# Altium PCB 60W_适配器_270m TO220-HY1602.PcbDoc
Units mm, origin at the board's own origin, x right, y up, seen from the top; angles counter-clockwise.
Board outline 43.1 x 72.7 mm, 2 copper layers (Top Layer, Bottom Layer); 70 components, 100 nets, 175 pads, 0 vias.
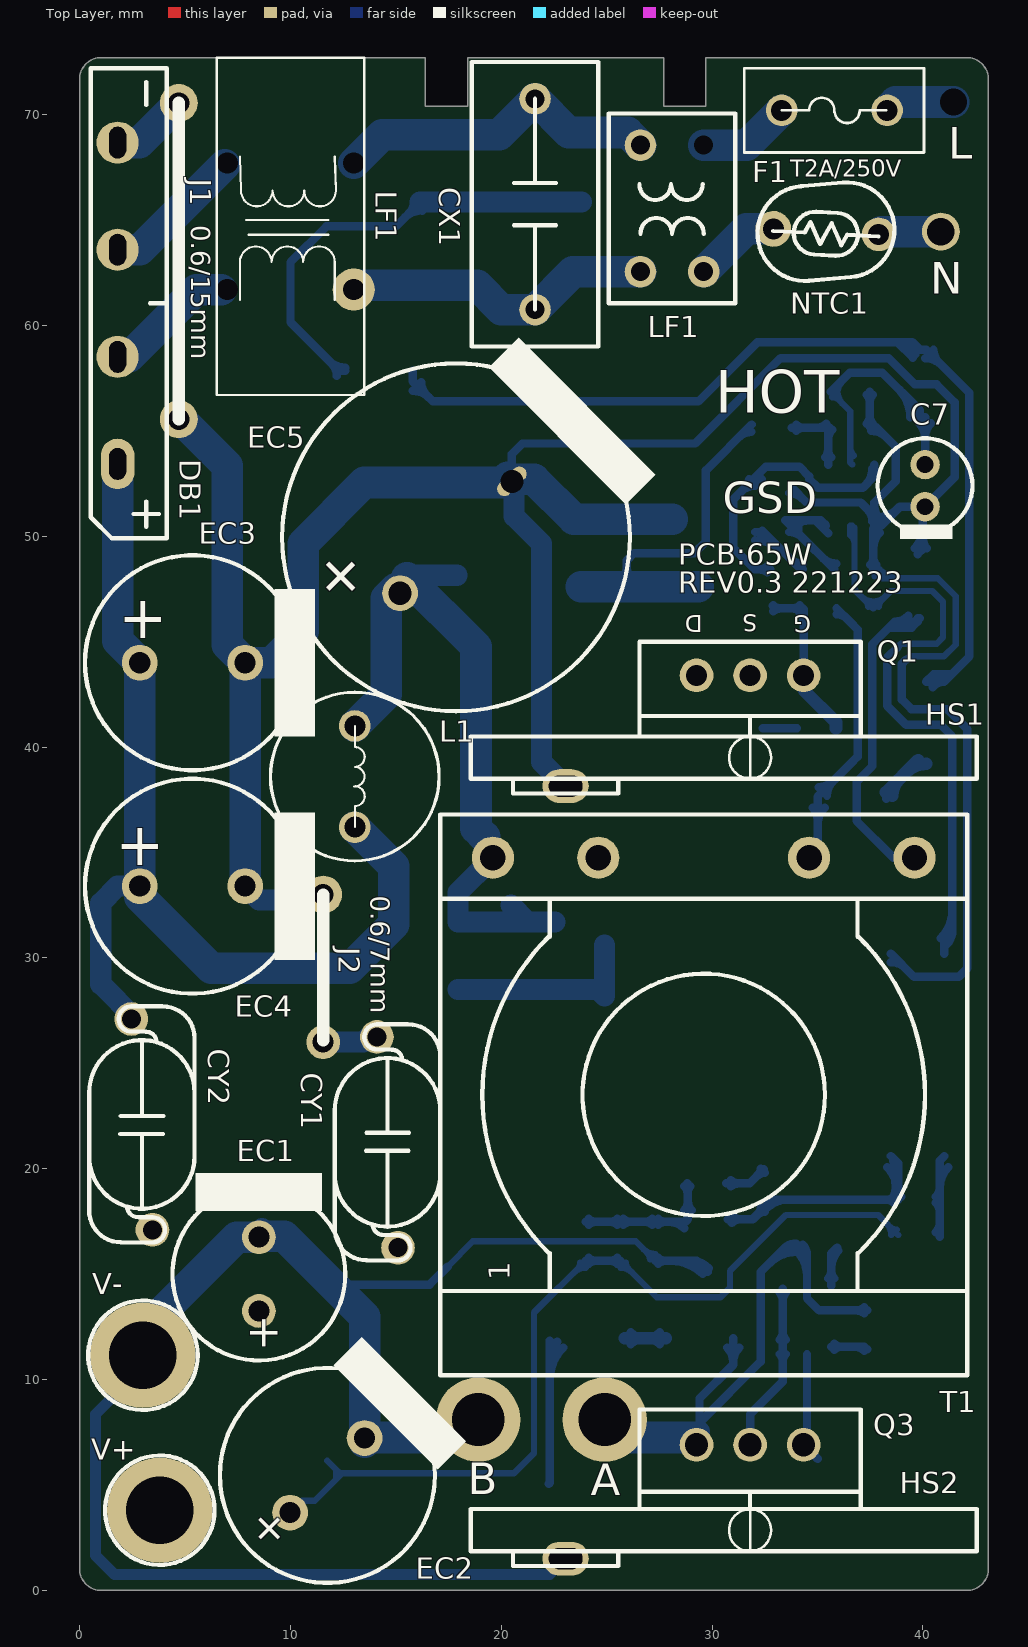
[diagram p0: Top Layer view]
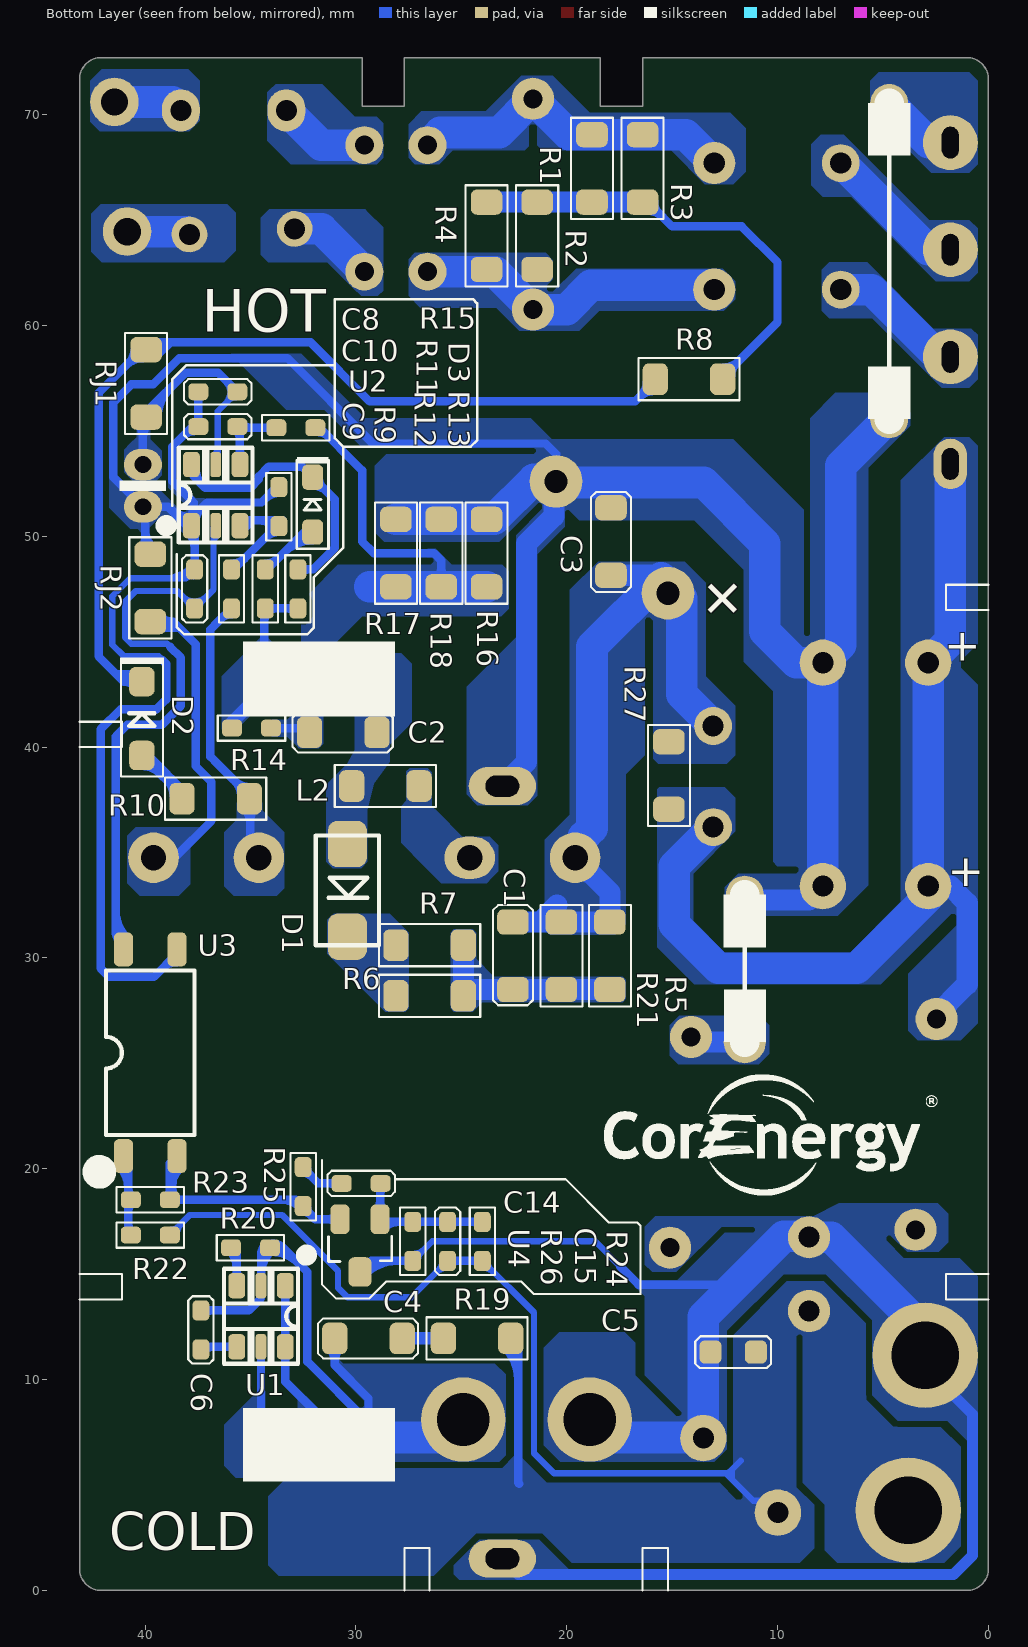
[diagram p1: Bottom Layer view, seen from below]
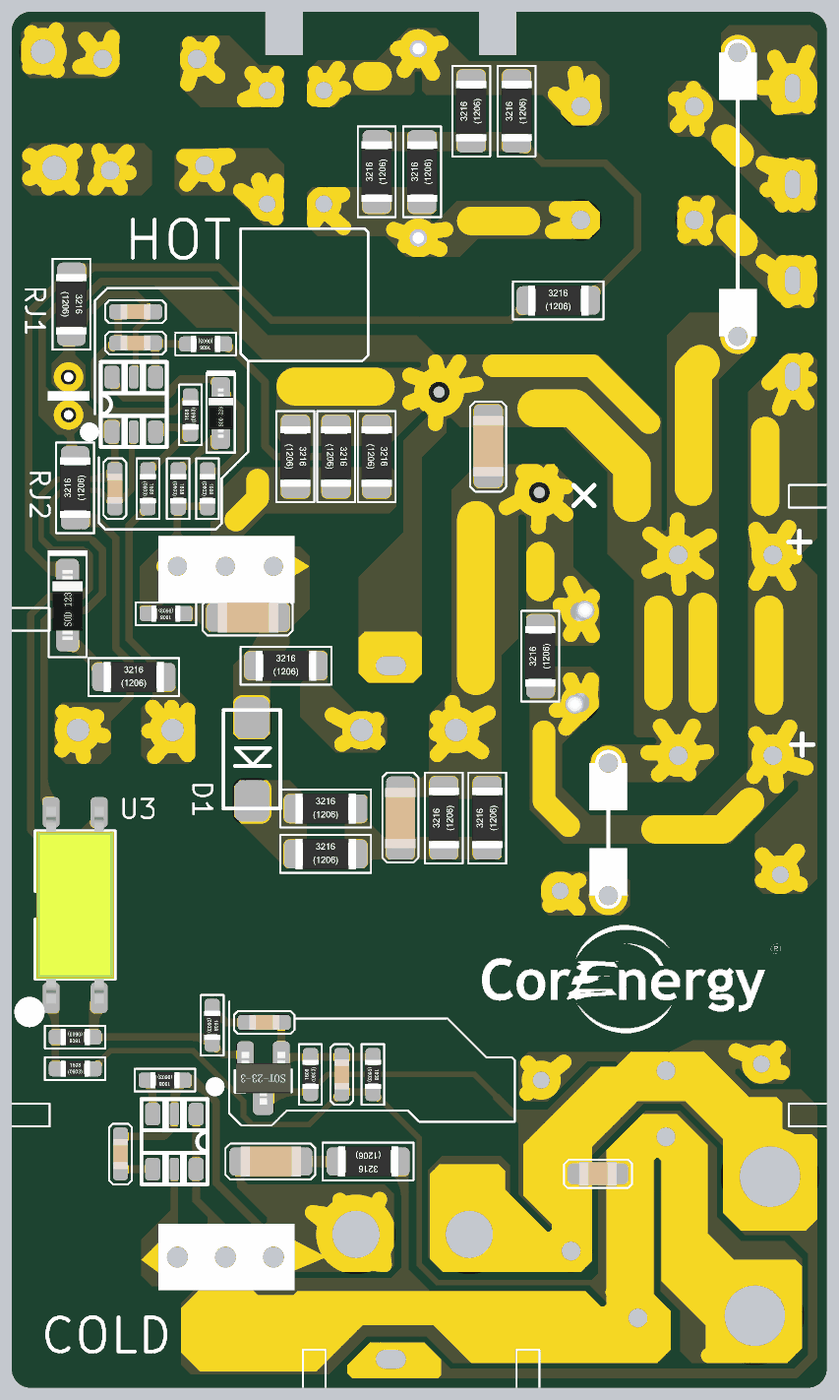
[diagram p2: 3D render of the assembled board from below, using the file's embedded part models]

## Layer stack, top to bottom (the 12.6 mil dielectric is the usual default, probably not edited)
Top Layer: signal copper 0.0356
Dielectric: dielectric 0.32, FR-4, Dk 4.8
Bottom Layer: signal copper 0.0356

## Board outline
0,1 ccw(c1,1) 1,0 42.1,0 ccw(c42.1,1) 43.1,1 43.1,71.7 ccw(c42.1,71.7) 42.1,72.7 29.7,72.7 29.7,70.4 27.7,70.4 27.7,72.7 18.4,72.7 18.4,70.4 16.4,70.4 16.4,72.7 1,72.7 ccw(c1,71.7) 0,71.7

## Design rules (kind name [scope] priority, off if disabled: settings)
AssemblyTestPointUsage [All] p1 off:
AssemblyTestpoint [All] p1 off: testpointundercomponent=TRUE minsize=1.016 maxsize=2.54 preferedsize=1.524 minholesize=0 maxholesize=1.016 preferedholesize=0.813 testpointgrid=0.025 usegrid=TRUE gridtolerance=0 allowsidetop=TRUE allowsidebottom=TRUE
Clearance [All] p1: gap=0.3
ComponentClearance [All] p1 off: gap=0.254 collisioncheckmode=3 verticalgap=0.254 showdistances=FALSE
DiffPairsRouting [All] p1 off: maxlimit=0.254 minlimit=0.254 mostfreqgap=0.254 maxuncoupledlength=12.7
FabricationTestPointUsage [All] p1 off: valid=0 allowmultiple=FALSE
FabricationTestpoint [All] p1 off: side=3 testpointundercomponent=TRUE minsize=1.016 maxsize=2.54 preferedsize=1.524 minholesize=0 maxholesize=1.016 preferedholesize=0.813 testpointgrid=0.025 allowsidetop=TRUE allowsidebottom=TRUE usegrid=TRUE gridtolerance=0
FanoutControl Fanout_BGA [IsBGA] p1 off: bgadir=Out bgaviamode=Centered fanoutstyle=Auto fanoutdirection=Alternating viagrid=0.025 // Fanout_BGA (Default Rule)
FanoutControl Fanout_LCC [IsLCC] p2 off: bgadir=Out bgaviamode=Centered fanoutstyle=Auto fanoutdirection=Alternating viagrid=0.025 // Fanout_LCC (Default Rule)
FanoutControl Fanout_SOIC [IsSOIC] p3 off: bgadir=Out bgaviamode=Centered fanoutstyle=Auto fanoutdirection=Alternating viagrid=0.025 // Fanout_SOIC (Default Rule)
FanoutControl Fanout_Small [(CompPinCount < 5)] p4 off: bgadir=Out bgaviamode=Centered fanoutstyle=Auto fanoutdirection=OutThenIn viagrid=0.025 // Fanout_Small (Default Rule)
FanoutControl Fanout_Default [All] p5 off: bgadir=Out bgaviamode=Centered fanoutstyle=Auto fanoutdirection=Alternating viagrid=0.025 // Fanout_Default (Default Rule)
Height [All] p1 off: minheight=0 maxheight=25.4 prefheight=12.7
HoleSize [All] p1 off: absolutevalues=TRUE maxlimit=2.54 minlimit=0.025 maxpercent=80.000 minpercent=20.000
HoleToHoleClearance [All] p1 off: gap=0.254 allowstackedmicrovias=TRUE
LayerPairs [All] p1 off: enforce=TRUE
MinimumSolderMaskSliver [All] p1 off: minsoldermaskwidth=0.254
NetAntennae [All] p1 off: netantennaetolerance=0
PasteMaskExpansion [All] p1 off: expansion=0
PlaneClearance [All] p1 off: clearance=0.508
PlaneConnect [All] p1 off: planeconnectstyle=Direct reliefexpansion=0.508 reliefentries=4 reliefconductorwidth=0.254 reliefairgap=0.254
PolygonConnect PolygonConnect_1 [All] p1: connectstyle=Direct reliefconductorwidth=0.254 reliefentries=4 polygonreliefangle="90 Angle" airgapwidth=0.254
RoutingCorners [All] p1 off: cornerstyle=45-Degree minsetback=2.54 maxsetback=2.54
RoutingLayers [All] p1 off: top layer_v5=TRUE bottom layer_v5=TRUE
RoutingPriority [All] p1 off: routingpriority=0
RoutingTopology [All] p1 off: topology=Shortest
RoutingVias [All] p1: holewidth=0.4 width=0.7 viastyle="Through Hole" minholewidth=0.3 minwidth=0.5 maxholewidth=1 maxwidth=1.5
SilkToSilkClearance [All] p1 off: silktosilkclearance=0.254
SilkToSolderMaskClearance [IsPad] p1 off: minsilkscreentomaskgap=0.254 clearancetoexposedcopper=TRUE
SolderMaskExpansion [All] p1 off: expansion=0.102
Width [All] p1: maxlimit=10 minlimit=0.2 preferedwidth=0.4
2 further rules are at their usual default settings.

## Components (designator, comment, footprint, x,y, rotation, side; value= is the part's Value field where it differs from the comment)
C1 "10nF/500V" 1206C 22.55,30.1 r270 bottom
C2 "10nF/500V" 1206C 30.6,40.7 r180 bottom (schematic designator C1)
C3 "10nF/500V" 1206C 17.9,49.75 r90 bottom
C4 "1nF/250V" 1206C 29.4,11.95 r180 bottom
C5 "4.7uF/25V 0805" 0805C 12.1,11.3 r180 bottom
C6 "0.22uF/50V" 0603C 37.35,12.35 r90 bottom
C7 "4.7uF 1206 50V D5*H10" EC-4X7-P2-C-1 40.1,52.4 r270 top
C8 "100nF 50V 0603" 0603C 36.55,56.85 r0 bottom
C9 "1nF/50V" 0603C 37.65,47.5 r90 bottom
C10 "100pF/50V" 0603C 36.55,55.2 r0 bottom
C14 "100nF/50v" 0603C 29.75,19.3 r180 bottom
C15 "100nF/50v" 0603C 25.65,16.55 r90 bottom (schematic designator C14)
CX1 "0.22uF/275Vac" XC-13X6-P10 21.6,65.75 r90 top
CY1 "1000pF/400Vac" YC-8X6-P10-V 14.6,21.25 r270 top
CY2 "1000pF/400Vac" YC-8X6-P10-V 2.95,22.1 r90 top (schematic designator CY1)
D1 "RS2M  SMAF" SMAF 30.4,33.2 r270 bottom
D2 "FR107 SOD123" 123 40.15,41.35 r270 bottom
D3 "1N4148 SOD323" 323 32.05,51.5 r270 bottom
DB1 "YBSM6008" BD-22X3.4-P5.08-+ 2,61.05 r270 top (schematic designator BD100)
EC1 "E - Cap" EC8 8.5,15 r90 top (schematic designator EC7)
EC2 "E - Cap" EC10 11.75,5.45 r45 top (schematic designator EC7)
EC3 "47uF/400V/13*19" EC10 5.35,44 r0 top (schematic designator EC1)
EC4 "47uF/400V/13*19" EC10 5.35,33.4 r0 top (schematic designator EC1)
EC5 "47uF/400V/13*19" EC-16X21-P7.5-C 17.85,49.95 r45 top (schematic designator EC1)
F1 "T2A/250V" FUSE 35.8,70.2 r90 top
HS1 "Comment" HS-PIN6 23.05,38.15 r180 top
HS2 "Comment" HS-PIN6 23.05,1.5 r180 top
J1 "Comment" JUMP-0.6/15 4.7,70.55 r270 top
J2 "Comment" JUMP-0.6/7.5 11.55,33 r270 top
L1 "HWR8*12/40uH" T8*10 13.05,38.6 r270 top
L2 "" 1206R 28.6,38.15 r180 bottom
LF1 "T6*3*3/100uH" T10*6*5 10,64.7 r90 top
LF1 "Comment" T9*5*3 28.1,65.55 r270 top
NTC1 "5D-7" NTC-6.5X4.5-P5 35.4,64.45 r185 top
Q1 "Comment" Cascode-TO220-3L-T 31.8,43.4 r180 top
Q3 "Comment" TO-220-3P-P2.54 31.8,6.9 r180 top
R1 "3.6M 1/2W" 1206R 18.8,67.45 r90 bottom
R2 "3.6M 1/2W" 1206R 21.4,64.25 r90 bottom
R3 "3.6M 1/2W" 1206R 16.4,67.45 r90 bottom
R4 "3.6M 1/2W" 1206R 23.8,64.25 r90 bottom
R5 "390K 1/2W" 1206R 17.95,30.1 r90 bottom
R6 "47R 1/2W" 1206R 26.5,28.2 r180 bottom
R7 "47R 1/2W" 1206R 26.5,30.6 r180 bottom
R8 "100K  1206" 1206R 14.2,57.45 r180 bottom
R9 "130K 0603" 0603R 35.9,47.5 r270 bottom
R10 "0805 磁珠/2.2R 0805" 1206R 36.65,37.55 r180 bottom
R11 "27K 0603" 0603R 33.65,51.4 r90 bottom
R12 "82R  1/10W 0603" 0603R 34.3,47.5 r270 bottom
R13 "10R 1/16W 0402" 0603R 32.75,47.5 r270 bottom
R14 "10K 0603" 0603R 34.95,40.9 r0 bottom
R15 "470R 0603" 0603R 32.85,55.15 r0 bottom
R16 "0R75 1/2W 1206" 1206R 23.8,49.2 r270 bottom
R17 "0R75 1/2W 1206" 1206R 28.1,49.2 r270 bottom
R18 "0R75 1/2W 1206" 1206R 25.95,49.2 r270 bottom
R19 "10R 1206" 1206R 24.25,11.95 r0 bottom
R20 "51K 0402" 0603R 35,16.25 r0 bottom
R21 "390K 1/2W" 1206R 20.25,30.1 r90 bottom (schematic designator R5)
R22 "2K" 0603R 39.75,16.85 r180 bottom
R23 "5.1K" 0603R 39.75,18.525 r0 bottom
R24 "24K" 0603R 24,16.55 r270 bottom
R25 "10K" 0603R 32.5,19.15 r270 bottom
R26 "3.16K" 0603R 27.3,16.55 r90 bottom
R27 "390K 1/2W" 1206R 15.15,38.65 r90 bottom (schematic designator R5)
RJ1 "150K/1206" 1206R 39.95,57.25 r270 bottom (schematic designator R9)
RJ2 "150K/1206" 1206R 39.75,47.55 r90 bottom (schematic designator R9)
T1 "Comment" EQ25 29.6,23.5 r0 top locked
U1 "MP6908/MK91808" SOT-23-6 34.5,13 r270 bottom
U2 "MK2697" SOT-23-6 36.65,51.95 r90 bottom
U3 "Comment" SO-4(P10)-超薄 39.75,25.5 r180 bottom
U4 "" SOT-23 29.8,16.35 r0 bottom

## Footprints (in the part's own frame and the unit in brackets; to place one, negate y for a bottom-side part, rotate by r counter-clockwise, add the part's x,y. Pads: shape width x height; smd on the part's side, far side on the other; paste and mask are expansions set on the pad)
123 [mm]
  rrect50% 1.4x1.2 smd mask+0.03: 1(1.75,0) 2(-1.75,0)
  silkscreen extent -2.9,-1.05 2.75,1.05, body extent -1.85,-0.8 1.85,0.8, height 1.2
323 [mm]
  rrect50% 1.2x1 smd mask+0.03: 1(1.3,0) 2(-1.3,0)
  silkscreen extent -2.25,-0.75 2.1,0.75, body extent -1.3,-0.65 1.3,0.65, height 1
0603C [mm]
  rrect50% 0.95x0.8 smd mask+0.03: 1(-0.925,0) 2(0.925,0)
  silkscreen extent -1.6,-0.6 1.6,0.6, body extent -0.8,-0.4 0.8,0.4, height 0.8
0603R [mm]
  rrect50% 0.95x0.8 smd mask+0.03: 1(-0.925,0) 2(0.925,0)
  silkscreen extent -1.6,-0.6 1.6,0.6, body extent -0.77,-0.42 0.78,0.43, height 0.45
0805C [mm]
  rrect50% 1.05x1.1 smd mask+0.03: 1(-1.075,0) 2(1.075,0)
  silkscreen extent -1.8,-0.75 1.8,0.75, body extent -1,-0.62 1,0.63, height 0.6
1206C [mm]
  rrect50% 1.2x1.5 smd mask+0.03: 1(-1.6,0) 2(1.6,0)
  silkscreen extent -2.4,-0.95 2.35,0.95, body extent -1.6,-0.8 1.6,0.8, height 0.79
1206R [mm]
  rrect50% 1.2x1.5 smd mask+0.03: 1(-1.6,0) 2(1.6,0)
  silkscreen extent -2.4,-1 2.4,1, body extent -1.6,-0.8 1.6,0.8, height 0.55
BD-22X3.4-P5.08-+ [mm]
  oval 2.4x1.6 hole 0.8 slot 1.5 at 0 deg mask+0.03: 1(7.62,-0.2)
  round 2 / inner round 2.6 / far side round 2.6 hole 0.8 slot 1.5 at 0 deg mask+0.03: 2(2.54,-0.2) 3(-2.54,-0.2) 4(-7.62,-0.2)
  silkscreen extent -11.15,-1.47 11.15,2.13
Cascode-TO220-3L-T [mm]
  round 1.6 / inner oval 1.6x2.6 / far side oval 1.6x2.6 hole 1 mask+0.03: 1(-2.54,0) 3(0,0)
  round 1.6 / inner oval 1.6x2.6 / far side oval 1.6x2 hole 1 mask+0.03: 2(2.54,0)
  silkscreen extent -5.25,-1.6 5.25,2.9, body extent -5.1,-1.35 5.1,2.85, height 1.1
EC8 [mm]
  round 1.6 / inner round 2 / far side round 2 hole 1 mask+0.03: 1(-1.75,0) 2(1.75,0)
  silkscreen extent -4.1,-4.1 4.8,4.1
EC10 [mm]
  round 1.7 / inner round 2.2 / far side round 2.2 hole 1 mask+0.03: 1(-2.5,0) 2(2.5,0)
  silkscreen extent -5.1,-5.1 5.8,5.1
EC-4X7-P2-C-1 [mm]
  round 1.4 / inner round 1.4 / far side oval 1.5x1.8 hole 0.8 mask+0.03: 1(-1,0) 2(1,0)
  silkscreen extent -2.25,-2.25 2.53,2.25, body extent -2.25,-2.25 2.25,2.25, height 8.6
EC-16X21-P7.5-C [mm]
  round 1.7 / inner round 2.5 / far side round 2.5 hole 1.1 mask+0.064: 1(-3.75,0)
  oval 1.7x0.7 / inner round 2.5 / far side round 2.5 hole 1.1 mask+0.064: 2(3.75,0)
  silkscreen extent -8.25,-8.25 8.8,8.25, body extent -8.1,-8.1 8.1,8.1, height 22.05
EQ25 [mm]
  round 2 on Mech2 mask+0.03: 1(-10,-11.25) 2(-5,-11.25) 3(0,-11.25) 4(5,-11.25) 5(10,-11.25) 8(0,11.25)
  round 2 / inner round 2 / far side round 2.4 hole 1.2 mask+0.03: 6(10,11.25) 7(5,11.25) 10(-10,11.25)
  round 2 / inner round 2 / far side oval 2.4x2 hole 1.2 mask+0.03: 9(-5,11.25)
  silkscreen extent -12.5,-13.3 12.5,13.3
FUSE [mm]
  round 1.5 / inner oval 2x1.8 / far side oval 2x1.8 hole 1 mask+0.03: 1(0,-2.5) 2(0,2.5)
  silkscreen extent -2,-4.25 2,4.28
HS-PIN6 [mm]
  oval 2.2x1.6 / inner oval 3.2x2.5 / far side oval 3.2x1.8 hole 1 slot 1.6 at 0 deg mask+0.03: 1(0,0)
  silkscreen extent -2.5,-0.35 2.5,0.35
JUMP-0.6/7.5 [mm]
  oval 3.5x2 on Mech2 mask+0.03: 0(0.75,0) 0(6.25,0)
  round 1.8 hole 1 mask+0.03: 1(0,0)
  round 1.6 / inner round 2 / far side round 2 hole 1 mask+0.03: 2(7,0)
  silkscreen extent 0,0 6.9,0
JUMP-0.6/15 [mm]
  oval 3.5x2 on Mech2 mask+0.03: 0(0.75,0) 0(14.25,0)
  round 1.8 hole 1 mask+0.03: 1(0,0) 2(15,0)
  silkscreen extent 0,0 15,0
NTC-6.5X4.5-P5 [mm]
  round 1.6 / inner round 1.7 / far side round 1.7 hole 1 mask+0.03: 1(-2.476,0.348)
  round 1.7 hole 1 mask+0.03: 2(2.476,-0.348)
  silkscreen extent -3.25,-2.25 3.25,2.25
SMAF [mm]
  rrect50% 2.2x1.85 smd: 1(-2.2,0) 2(2.2,0)
  silkscreen extent -2.6,-1.5 2.6,1.5
SO-4(P10)-超薄 [mm]
  rrect50% 0.9x1.6 smd mask+0.03: 1(-1.27,-4.9) 2(1.27,-4.9) 3(1.27,4.9) 4(-1.27,4.9)
  silkscreen extent -2.82,-6.05 2.1,3.9, body extent -2.05,-5.2 2.05,5.2, height 2.5
SOT-23 [mm]
  rrect50% 0.9x1.4 smd mask+0.03: 1(-0.95,-1.25) 3(0.95,-1.25)
  rrect50% 1.1x1.4 smd mask+0.03: 2(0,1.25)
  silkscreen extent -1.5,-0.45 1.5,0.75, body extent -1.45,-1.4 1.45,1.4, height 1.2
SOT-23-6 [mm]
  rrect50% 1.2x0.8 smd mask+0.03: 1(-1.45,1.15) 3(-1.45,-1.15) 4(1.45,-1.15) 6(1.45,1.15)
  rrect50% 1.2x0.5 smd mask+0.03: 2(-1.45,0) 5(1.45,0)
  silkscreen extent -3.15,-1.75 2.25,2.4
T8*10 [mm] "磁环电感"
  round 1.5 / inner round 1.5 / far side round 1.8 hole 1: 1(-2.4,0) 2(2.4,0)
  silkscreen extent -4,-4 4,4, body extent -3.5,-3.5 3.5,3.5, height 10.92
T9*5*3 [mm]
  round 1.5 / inner round 1.8 / far side round 1.8 hole 0.9 mask+0.03: 1(3,1.5) 3(-3,-1.5) 4(3,-1.5)
  round 0 / inner round 1.8 / far side round 1.8 hole 0.9 mask+0.03: 2(-3,1.5)
  silkscreen extent -4.5,-3 4.5,3
T10*6*5 [mm] "磁环电感"
  round 0 / inner round 1 / far side round 1.8 hole 1: 1(3,3)
  round 2 hole 1: 2(-3,-3)
  round 0 / inner round 1 / far side round 2 hole 1: 3(3,-3)
  round 0 / inner round 1.8 / far side round 1.8 hole 1: 4(-3,3)
  silkscreen extent -8,-3.5 8,3.5
TO-220-3P-P2.54 [mm]
  round 1.6 / inner oval 1.9x2.6 / far side oval 1.9x2.6 hole 1.1 mask+0.03: 1(-2.54,0) 2(0,0) 3(2.54,0)
  silkscreen extent -5.25,-1.67 5.25,3.05
XC-13X6-P10 [mm]
  round 1.5 / inner round 2 / far side round 2 hole 0.9 mask+0.03: 1(-5,0) 2(5,0)
  silkscreen extent -6.75,-3 6.75,3, body extent -6.5,-3 6.5,3, height 11.2
YC-8X6-P10-V [mm]
  round 1.6 / inner round 2 / far side round 2 hole 0.9 mask+0.03: 1(-5,-0.5) 2(5,0.5)
  silkscreen extent -5.6,-2.5 5.6,2.5

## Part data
C1 C2 C3 C4 C5 C6 C8 C9 C10 C14 C15: library part CAPACITOR
C7: library part E-CAP
CX1: library part R21030006, "R21030006/工业C/消费A/金属膜电容/0.1uF±10%/275Vac/X2/聚炳烯/引脚间距10mm"
CY1 CY2: library part R21020185, "R21020185/工业C/消费C/瓷片电容/220pF±10%/400Vac/Y1/Y5P/P=10mm/Y脚编带"
D1 D2 D3: library part DIODE
DB1: library part BRIDGE, "1000V/6A， YBS3,YANGJIE(扬杰)"
EC1 EC2: "Electroytic Capacitor, 100uF/35V, ±20%, 105℃，Φ 6.5 * 12.0 mm"
EC3 EC4 EC5: library part R21010448, "R21010448/工业B/消费B/铝电解电容/105℃/33uF/400V/φ13*25"
F1: library part FUSE, "FUSE"
L1: library part IND-C, "ferrite inductor"
L2: library part Inductor, "Inductor"
LF1: library part L-T12*6*6
NTC1: library part RT-NTC-SCH
R1 R2 R3 R4 R5 R6 R7 R8 R9 R10 R11 R12 R13 R15 R16 R17 R18 R19 R20 R21 R22 R23 R24 R25 R26 R27: library part RESISTOR
R14: library part RES, "RES"
RJ1 RJ2: library part R20140036, "R20140036/工业A/消费A/贴片电阻/1/4W/150KΩ±5%/1206"
U1: library part MK91808
U4: library part "IC TL431", "IC"

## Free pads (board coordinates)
  round 5 hole 3.2: 0(3,11.15) 0(3.8,3.8)
  round 1.8 / inner round 2.3 / far side round 2.3 hole 1.3: 3(40.85,64.45)
  round 0 / inner round 2.3 / far side round 2.3 hole 1.3: 3(41.45,70.6)
  round 4 hole 2.5: B(18.9,8.1) B(24.9,8.1)

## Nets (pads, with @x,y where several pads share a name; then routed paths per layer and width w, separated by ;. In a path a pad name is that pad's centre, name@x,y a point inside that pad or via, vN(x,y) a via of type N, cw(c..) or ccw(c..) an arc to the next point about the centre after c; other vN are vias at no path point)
12V: 
111: 
115: 
116: F1.2 LF1.2@29.6,68.55 | length 4.4
  Bottom Layer w1.5: LF1.2@29.6,68.55 31.65,68.55 F1.2
117: LF1.1@29.6,62.55 NTC1.2 | length 4.1
  Bottom Layer w1.5: LF1.1@29.6,62.55 31.631,64.581 NTC1.2
AGND: 
COMP: C9.1 U2.2 U3.4 | length 35.2
  Bottom Layer w0.3: U2.2@36.55,50.5 36.55,50.05 36.75,49.85 ; U2.2@36.579,50.079 cw(c36.167,49.667) 36.75,49.667 ; U2.2@36.607,50.06 cw(c36.5,49.834) 36.75,49.834 ; U2.2 36.75,50.4 36.75,49.85 ; U2.2@36.731,50.091 ccw(c36.882,49.982) 36.75,49.85 ; 37.095,47.13 ccw(c37.65,47.685) 37.65,46.9 ccw(c37.65,47.685) 38.205,47.13 ; C9.1@37.276,46.949 cw(c36.978,46.65) C9.1@37.4,46.65 ; C9.1@37.9,46.65 cw(c38.322,46.65) C9.1@38.024,46.949 ; 38.81,44.75 38.96,44.9 40.65,44.9 40.95,45.2 40.95,46.9 40.45,47.4 38.475,47.4 C9.1 36.75,47.475 36.75,49.85
  Bottom Layer w0.4: 38.81,44.75 38.3,44.24 38.3,41.96 39.21,41.05 40.85,41.05 41.375,40.525 ; U3.4@40.843,30.927 ccw(c39.499,32.271) 41.4,32.271 ; U3.4@41.02,30.2 41.02,30.77 41.4,31.15 41.4,40.5 ; U3.4@41.126,30.644 ccw(c40.465,31.305) 41.4,31.305
D: 
DGND: 
FB_IC1: 
GND: C3.2 C7.2 C8.2 C9.2 C10.2 CY1.1 DB1.4 EC3.2 EC4.2 EC5.2 HS1.1 J1.1 J1.2 J2.1 J2.2 R11.2 R16.1 R17.1 R18.1 RJ2.1 RJ2.2 T1.6 U2.1 U3.3 | length 185.6
  Bottom Layer w0.3: C9.2@37.615,48.315 ccw(c38.374,49.074) 38.374,48 ; C9.2 38.075,48 ; C9.2@37.706,48.106 cw(c37.794,47.719) 38.075,48 ; C9.2@37.827,48.527 ccw(c39.099,49.799) 39.099,48 ; C9.2@37.9,48.35 ccw(c38.322,48.35) C9.2@38.024,48.051 ; 39.2,44.15 39.35,44.3 41,44.3 41.55,44.85 41.55,47.149 40.699,48 38.075,48
  Bottom Layer w0.4: EC5.2@20.502,52.802 20.502,53.902 21,54.4 29.2,54.4 33.25,58.45 38.369,58.45 39.619,57.2 40.65,57.2 41.5,56.35 41.5,52.8 C7.2 C7.2@40,51.4 ; R11.2@33.65,52.05 cw(c33.65,51.145) 34.29,51.785 ; R11.2@33.8,52.275 34.475,51.6 37.05,51.6 U2.1@37.7,50.95 ; C10.2@37.334,55.341 ccw(c36.992,55.683) 37.475,55.683 ccw(c37.958,55.683) C10.2@37.616,55.341 ; C8.2@37.334,56.709 cw(c36.992,56.367) 37.475,56.367 cw(c37.958,56.367) C8.2@37.616,56.709 ; 37.353,51.297 cw(c36.755,50.7) U2.1@37.6,50.7 ; C8.2 C10.2 37.75,55.2 38.7,54.25 38.7,52.6 37.7,51.6 U2.1@37.7,50.5 ; C9.2@37.509,48.641 ccw(c37.167,48.983) 37.65,48.983 ccw(c38.133,48.983) C9.2@37.791,48.641 ; C10.2@37.55,55 cw(c37.55,54.034) 38.233,54.717 ; 37.6,44.4 37.6,44.88 38.385,45.665 ; 37.6,44.53 37.6,39.1 37.25,38.75 36.85,38.35 36.85,36.5 38.6,34.75 T1.6 ; C9.2 37.65,50.35 U2.1 38,50.5 38.9,51.4 C7.2@40,51.4 ; 37.65,49.455 cw(c38.645,49.455) U2.1@37.941,50.159 ; 37.7,51.424 ccw(c38.524,51.424) U2.1@37.941,50.841 ; U2.1@37.8,50.9 ccw(c37.8,52.349) 38.824,51.324 ; U3.3@38.48,29.8 cw(c38.48,28.834) 39.163,29.517 ; U3.3@38.48,30.2 39.58,29.1 41.7,29.1 42.1,29.5 42.1,40.85 41.15,41.8 39.45,41.8 39,42.25 39,43.95 39.2,44.15 ; RJ2.1@39.31,45.675 ccw(c38.67,45.069) 38.67,45.95 ; RJ2.1@39.31,46.225 cw(c38.67,46.831) 38.67,45.95 ; RJ2.2@39.617,49.433 ccw(c38.693,50.357) 40,50.357 ; RJ2.1@39.75,46.1 RJ2.1@39.85,46.1 ; RJ2.2 40,49.4 C7.2@40,51.4 ; 40,49.874 ccw(c40.624,49.874) RJ2.2@40.183,49.433 ; 38.385,45.665 39.465,45.665 RJ2.1 38.67,45.95 ; 38.385,45.665 38.67,45.95
  Bottom Layer w1: EC4.2 8.5,32.75 J2.1@11.65,32.75 ; J2.2 13.45,26 CY1.1@13.7,26.25 ; EC5.2@20.2,52.552 20.6,52.152 20.6,50.95 21.9,49.65 21.9,39.3 HS1.1
  Bottom Layer w1.5: DB1.4 2.82,68.67 J1.1 ; J1.2@5.15,55.2 7,53.35 7,44.85 EC3.2 ; EC4.2 EC3.2 ; EC5.2@20.2,52.552 13.502,52.552 10.6,49.65 10.6,45.5 9.1,44 EC3.2 ; EC5.2@20.302,52.802 EC5.2@20.376,52.727 ; EC5.2@20.402,52.702 21.548,52.702 23.45,50.8 R16.1 R18.1 R17.1
HV: C1.1 C3.1 EC5.1 L1.1 R5.2 R21.2 R27.2 T1.10 | length 33
  Bottom Layer w1: EC5.1@15.525,48.025 15.65,48.15 C3.1 ; T1.10 17.95,33.1 R5.2 R21.2 21.25,31.7 ; 20.45,32.5 21.25,31.7 ; C1.1 21.25,31.7
  Bottom Layer w1.5: L1.1 14.55,42.5 14.55,47.05 EC5.1@14.998,47.498 ; EC5.1@15.525,48.025 18.8,44.75 18.8,36.15 T1.10@19.2,35.75
IC1_CS: 
IC1_GD: 
L: 
L1: 
N: 
N1: 
NetC1_1: 
NetC1_2: C1.2 R5.1 R6.2 R7.2 R21.1 | length 9.5
  Bottom Layer w1: R5.1 R21.1 C1.2 24.6,28.5 R6.2 R7.2
NetC2_1: 
NetC2_2: L2.2 T1.9
NetC4_1: 
NetC4_2: C4.2 R19.2 | length 5
  Bottom Layer w0.4: R19.2@26.133,11.667 cw(c26.816,10.984) 26.816,11.95 cw(c26.816,12.916) R19.2@26.133,12.233 ; C4.2@27.517,11.667 ccw(c26.834,10.984) 26.834,11.95 ccw(c26.834,12.916) C4.2@27.517,12.233
  Bottom Layer w0.6: R19.2 C4.2
NetC5_1: 
NetC6_1: C6.1 U1.4 | length 3
  Bottom Layer w0.4: U1.4 37.225,11.55 C6.1 ; U1.4@35.791,11.409 cw(c36.133,11.067) 36.133,11.55 cw(c36.133,12.033) U1.4@35.791,11.691 ; 36.746,11.55 cw(c36.746,10.896) C6.1@37.209,11.359
NetC7_1: C7.1 C8.1 D2.2 R8.1 RJ1.1 RJ1.2 U2.5 | length 68.7
  Bottom Layer w0.3: C8.1 36.55,55.925 36.55,53.5 U2.5 ; C8.1@35.7,56.6 cw(c35.7,56.178) C8.1@35.999,56.476 ; C8.1@35.95,56.85 ccw(c36.735,56.85) 36.18,56.295 ; 36.55,54.233 ccw(c37.133,54.233) U2.5@36.721,53.821
  Bottom Layer w0.4: R8.1@15.8,56.9 cw(c15.8,55.814) 16.568,56.582 ; R8.1@15.8,57.85 15.8,57.35 16.75,56.4 29.35,56.4 32.15,59.2 38.8,59.2 ; R8.1@16.2,57.3 ccw(c17.045,57.3) 16.447,56.703 ; C8.1 36.525,57.75 38.079,57.75 39.85,55.979 RJ1.2@39.85,55.65 ; C8.1@35.9,56.85 cw(c36.564,56.85) 36.094,57.319 ; 38.849,56.979 cw(c37.52,55.65) RJ1.2@39.4,55.65 ; RJ1.1@39.525,58.475 38.8,59.2 ; 39.532,56.296 cw(c38.886,55.65) RJ1.2@39.8,55.65 ; RJ1.1@39.629,58.621 39.05,59.2 ; RJ1.2@39.817,55.367 cw(c39.134,54.684) 40.1,54.684 cw(c41.066,54.684) RJ1.2@40.383,55.367 ; C7.1@40.1,54.05 RJ1.2@40.1,55.65 ; RJ1.1@40.1,58.45 cw(c40.1,57.364) 40.868,58.132 ; D2.2@40.458,42.845 cw(c41,42.397) 41,43.1 ; D2.2@40.458,43.355 ccw(c41,43.803) 41,43.1 ; RJ1.1@40.5,58.85 ccw(c41.345,58.85) 40.747,58.253 ; 38.8,59.2 39.05,59.2 ; 39.05,59.2 39.5,59.2 39.85,58.85 RJ1.1 40.15,58.85 42.2,56.8 42.2,44.3 41.35,43.45 ; 41,43.1 D2.2 40.5,43.45 41.35,43.45 ; 41,43.1 41.35,43.45
NetC7_2: 
NetC10_1: C10.1 R15.2 U2.4 | length 6.1
  Bottom Layer w0.4: R15.2 35.575,55.15 35.5,55.075 U2.4 ; R15.2@33.991,55.009 cw(c34.333,54.667) 34.333,55.15 cw(c34.333,55.633) R15.2@33.991,55.291 ; 34.946,55.15 ccw(c34.946,55.804) C10.1@35.409,55.341 ; U2.4@35.359,53.741 ccw(c35.017,54.083) 35.5,54.083 ccw(c35.983,54.083) U2.4@35.641,53.741 ; 35.5,54.596 cw(c36.154,54.596) C10.1@35.691,55.059
NetC11_1: C2.1 Q1.3 R14.1 R15.1 R16.2 R17.2 R18.2 | length 21.7
  Bottom Layer w0.4: R18.2@25.667,47.883 ccw(c24.984,48.566) 25.95,48.566 ccw(c26.916,48.566) R18.2@26.233,47.883 ; R18.2 25.95,48.85 26.3,49.2 29.15,49.2 29.7,49.75 29.7,53.125 R15.1@31.875,55.3 ; 31.295,54.72 cw(c31.85,54.165) R15.1@31.85,54.95 ; Q1.3 32,43.2 Q1.3@32.175,43.025 ; C2.1@32.4,40.9 R14.1
  Bottom Layer w1.5: R16.2 R18.2 R17.2 29.35,47.6
NetC12_1: C2.2 D1.1 L2.1 Q1.2
NetC14_1: C14.1 R25.1 | length 3.6
  Bottom Layer w0.4: C14.1 31.775,19.3 R25.1@32.45,19.975 ; C14.1@30.891,19.159 cw(c31.233,18.817) 31.233,19.3 cw(c31.233,19.783) C14.1@30.891,19.441 ; 32.116,19.641 cw(c32.5,19.257) R25.1@32.5,19.8 ; R25.1@32.176,19.701 ccw(c31.878,20) R25.1@32.3,20
NetC14_2: C14.2 C15.2 R24.1 R26.2 U4.1 | length 12.9
  Bottom Layer w0.4: R24.1 28.725,17.475 U4.1 28.85,19.275 C14.2 ; R24.1@24.141,17.334 cw(c24.483,16.992) 24.483,17.475 cw(c24.483,17.958) R24.1@24.141,17.616 ; C15.2@25.509,17.334 ccw(c25.167,16.992) 25.167,17.475 ccw(c25.167,17.958) C15.2@25.509,17.616 ; C15.2@25.791,17.334 cw(c26.133,16.992) 26.133,17.475 cw(c26.133,17.958) C15.2@25.791,17.616 ; R26.2@27.159,17.334 ccw(c26.817,16.992) 26.817,17.475 ccw(c26.817,17.958) R26.2@27.159,17.616 ; R26.2@27.441,17.334 cw(c27.783,16.992) 27.783,17.475 cw(c27.783,17.958) R26.2@27.441,17.616 ; 27.945,17.475 cw(c27.945,16.445) U4.1@28.673,17.173 ; U4.1@28.673,18.027 ccw(c28.246,18.454) 28.85,18.454 ccw(c29.454,18.454) U4.1@29.027,18.027 ; C14.2@28.684,19.159 cw(c28.282,18.757) 28.85,18.757 ; 28.85,18.878 cw(c29.247,18.878) C14.2@28.966,19.159
NetC200_2: 
NetC201_2: 
NetC202_2: 
NetC203_2: 
NetC204_2: 
NetC205_2: 
NetC206_1: 
NetC207_1: 
NetC208_1: 
NetC208_2: 
NetC209_1: 
NetC209_2: 
NetC210_2: 
NetC211_2: 
NetC219_1: 
NetC220_1: 
NetCX1_1: CX1.1 LF1.2@13,61.7 LF1.4@26.6,62.55 R2.1 R4.1 | length 14.9
  Bottom Layer w1.5: LF1.2@13,61.7 13.2,61.9 18.85,61.9 20,60.75 CX1.1 23.4,62.55 LF1.4@26.6,62.55
NetCX1_2: CX1.2 LF1.3 R1.2 R3.2 | length 15.8
  Bottom Layer w1.5: LF1.3@13,67.7 14.35,69.05 R3.2 19.9,69.05 CX1.2 23.2,69.15 26,69.15 LF1.3@26.6,68.55
NetD1_2: D1.2 R6.1 R7.1
NetD2_1: D2.1 R10.1 | length 4.4
  Bottom Layer w0.4: R10.1 R10.1@38.25,37.85
  Bottom Layer w0.6: R10.1@38.25,37.85 D2.1@39.775,39.375 ; R10.1@38.55,37.7 cw(c39.636,37.7) 38.868,38.468 ; 39.211,38.811 cw(c40.15,37.872) D2.1@40.15,39.2
NetD3_1: D3.2 R13.1 U2.6 | length 16.1
  Bottom Layer w0.4: 31.367,52.117 cw(c32.05,51.434) D3.2@32.05,52.4 ; D3.2@31.609,52.359 ccw(c31.267,52.7) D3.2@31.75,52.7 ; D3.2 32.55,53.3 34.14,53.3 34.6,52.84 34.6,52.71 35.01,52.3 37.15,52.3 37.7,52.85 U2.6@37.7,53.4 ; D3.2@32.35,52.7 31.95,52.7 31,51.75 31,49.45 32.025,48.425 R13.1 ; R13.1@32.609,48.284 ccw(c32.267,47.942) 32.267,48.425 ccw(c32.267,48.908) R13.1@32.609,48.566 ; 37.282,52.432 ccw(c36.514,53.2) U2.6@37.6,53.2
NetD3_2: D3.1 R12.1 | length 5.6
  Bottom Layer w0.4: D3.1@32.05,49.8 cw(c32.05,47.893) 33.399,49.241 ; D3.1 cw(c32.05,49.259) 32.716,49.924 ; D3.1@32.37,50.27 34.215,48.425 R12.1 ; 33.685,48.955 ccw(c34.3,49.569) R12.1@34.3,48.7
NetD5_1: 
NetD200_1: 
NetD201_1: 
NetD202_1: 
NetD203_1: 
NetDB1_1: DB1.2 LF1.4@7,61.7 | length 5.7
  Bottom Layer w1.5: DB1.2@2.35,58.51 5.54,61.7 LF1.4@6.7,61.7
NetDB1_2: DB1.3 LF1.1@7,67.7 | length 6.2
  Bottom Layer w1.5: DB1.3@2.35,63.59 2.84,63.59 LF1.1@6.875,67.625
NetDB1_3: 
NetDB1_4: CY2.2 DB1.1 EC3.1 EC4.1 L1.2 R27.1 | length 49
  Bottom Layer w1: CY2.2@2.65,27.1 1,28.75 1,32.6 1.8,33.4 EC4.1
  Bottom Layer w1.5: DB1.1 1.8,45.05 EC3.1 EC4.1 2.85,32.9 6.25,29.5 12.8,29.5 14.9,31.6 14.9,34.35 L1.2
NetF1_1: F1.1 pad.3@41.45,70.6 | length 3.3
  Bottom Layer w1.5: F1.1 38.7,70.6 pad.3@41.45,70.6
NetF1_2: 
NetNTC1_1: NTC1.1 pad.3@40.85,64.45 | length 3
  Bottom Layer w1.5: NTC1.1 38.027,64.45 pad.3@40.85,64.45
NetP1_1: 
NetQ1_1: 
NetQ1_3: 
NetQ2_G: Q1.1 R12.2 R13.2 R14.2 | length 10.3
  Bottom Layer w0.4: R13.2@32.871,46.696 32.993,46.575 R12.2 34.34,46.535 Q1.1 ; R13.2@32.891,46.434 cw(c33.233,46.092) 33.233,46.575 cw(c33.233,47.058) R13.2@32.891,46.716 ; Q1.1@34.025,43.085 Q1.1 ; R12.2@34.159,46.359 cw(c33.721,45.921) 34.34,45.921 ; R12.2@34.159,46.434 ccw(c33.817,46.092) 33.817,46.575 ccw(c33.817,47.058) R12.2@34.159,46.716 ; Q1.1@34.34,42.71 Q1.1
  Bottom Layer w0.6: Q1.1@34.34,42.71 35.875,41.175 R14.2
NetQ3_4: Q3.1 U1.5 | length 5.3
  Bottom Layer w0.4: U1.5@34.5,11.2 34.5,7.06 Q3.1 Q3.1@35,6.24
NetR1_1: R1.1 R2.2 R3.1 R4.2 R8.2 | length 24.4
  Bottom Layer w0.4: 11.832,58.318 ccw(c12.6,59.086) R8.2@12.6,58 ; 11.953,58.197 cw(c11.355,57.6) R8.2@12.2,57.6 ; R8.2@12.6,57.85 12.3,57.85 10,60.15 10,63 11.7,64.7 15,64.7 R3.1@16.15,65.85 ; 15.396,65.096 cw(c16.25,64.243) R3.1@16.25,65.45 ; 15.638,65.338 ccw(c15.126,65.85) R3.1@15.85,65.85
  Bottom Layer w1: R3.1@16.15,65.85 R4.2
NetR7_1: 
NetR8_1: 
NetR9_1: R9.1 R11.1 U2.3 | length 9.7
  Bottom Layer w0.4: R11.1@33.65,50.2 cw(c33.65,49.295) 34.29,49.935 ; R11.1@33.791,50.409 cw(c34.616,49.584) 34.616,50.75 ; 35.26,48.965 ccw(c35.9,49.605) R9.1@35.9,48.7 ; U2.3@35.359,50.559 ccw(c34.896,50.096) 34.896,50.75 ; U2.3@35.4,50.5 35.15,50.75 34.896,50.75 ; U2.3@35.5,50.146 34.896,50.75 ; R9.1@35.8,48.425 34.088,50.138 ; 34.088,50.138 34.088,50.638 34.2,50.75 ; 34.088,50.138 33.475,50.75 34.2,50.75 ; 34.2,50.75 34.896,50.75
NetR9_2: R9.2 R10.2 T1.7 | length 16.7
  Bottom Layer w0.4: T1.7 35,35.15 35,37.65 36.55,39.2 36.9,39.55 36.9,45.575 36.55,45.925 R9.2 ; R10.2@34.767,37.117 cw(c34.205,36.555) 35,36.555 ; 35,36.314 cw(c36.136,36.314) R10.2@35.333,37.117 ; R10.2@35.05,38.1 ccw(c35.05,39.066) 35.733,38.383 ccw(c36.416,37.7) R10.2@35.45,37.7 ; R9.2@35.9,46.3 cw(c35.9,45.636) 36.369,46.106
NetR20_2: R20.2 U1.3 | length 3.6
  Bottom Layer w0.4: U1.3@35.509,14.791 ccw(c35.167,15.133) 35.65,15.133 ccw(c36.133,15.133) U1.3@35.791,14.791 ; U1.3 35.65,15.975 R20.2 ; 35.65,15.284 cw(c36.816,15.284) R20.2@35.991,16.109
NetR21_1: 
NetR22_1: R22.1 R23.2 U3.1 | length 6.5
  Bottom Layer w0.4: R22.1@40.609,16.991 ccw(c40.146,17.454) 40.8,17.454 ; R23.2@40.609,18.384 cw(c40.146,17.921) 40.8,17.921 ; R23.2@40.609,18.666 ccw(c40.146,19.129) 40.8,19.129 ; R22.1@40.8,16.775 40.8,20.38 U3.1 ; 40.8,19.115 cw(c42.155,19.115) U3.1@41.197,20.073
NetR23_1: R23.1 R25.2 U3.2 U4.3 | length 17.7
  Bottom Layer w0.4: U4.3 31.925,17.6 32.45,18.125 32.85,18.525 R23.1 38.825,20.255 U3.2 ; U4.3@30.927,17.423 cw(c31.354,16.996) 31.354,17.6 cw(c31.354,18.204) U4.3@30.927,17.777 ; 32.116,17.791 cw(c32.5,17.407) R25.2@32.5,17.95 ; R25.2@32.176,17.851 ccw(c31.878,18.15) R25.2@32.3,18.15 ; R25.2@32.641,18.159 cw(c33.526,17.274) 33.526,18.525 ; U3.2@38.303,20.073 cw(c37.044,18.814) R23.1@38.825,18.814 ; R23.1@38.577,18.625 ccw(c37.724,19.118) 38.675,19.373 ; U3.2@38.586,20.356 cw(c38.009,19.779) 38.825,19.779 ; R23.1@38.609,18.384 ccw(c38.267,18.042) 38.267,18.525 ccw(c38.267,19.008) R23.1@38.609,18.666 ; R23.1@38.684,18.666 ccw(c38.342,19.008) 38.825,19.008 ccw(c39.308,19.008) R23.1@38.966,18.666
NetR200_2: 
NetR201_2: 
NetR202_2: 
NetR203_1: 
NetR204_1: 
NetR205_1: 
NetR206_1: 
NetR211_2: 
NetR212_1: 
NetRX1_1: 
NetU201_3: 
NULL1: 
OPT: 
SGND: C5.1 CY1.2 CY2.1 EC1.2 EC2.2 HS2.1 pad.0@3,11.15 pad.B@18.9,8.1 R26.1 U4.2 | length 82.3
  Bottom Layer w0.3: 17.45,15.35 18.65,16.55 26.375,16.55 R26.1 ; 26.745,16.18 ccw(c27.3,16.735) R26.1@27.3,15.95 ; R26.1@26.926,15.999 cw(c26.628,15.7) R26.1@27.05,15.7
  Bottom Layer w0.4: 12.9,14.5 16.6,14.5 17.45,15.35 ; R26.1 29.275,15.625 U4.2 ; R26.1@27.441,15.484 cw(c27.783,15.142) 27.783,15.625 cw(c27.783,16.108) R26.1@27.441,15.766 ; 28.05,15.625 cw(c28.05,13.5) U4.2@29.553,15.003 ; 29.015,15.625 cw(c29.015,14.465) U4.2@29.835,15.285
  Bottom Layer w0.5: pad.0@3,10.6 0.75,8.35 0.75,1.65 1.65,0.75 22.3,0.75 HS2.1
  Bottom Layer w1: CY2.1 CY2.1@3.55,17.2 ; EC1.2@8.25,16.75 EC1.2@8.65,17.15
  Bottom Layer w1.5: pad.0@3.1,10.8 3.1,12.4 7.45,16.75 EC1.2@8.25,16.75 ; EC1.2@9,16.8 9.7,16.8 13.518,12.982 13.518,7.018 13.75,7.25 pad.B@18.9,7.25
VC1: 
VC2: 
VFB_IC2: 
VIN: C5.2 C15.1 EC1.1 EC2.1 pad.0@3.8,3.8 Q3.2 R19.1 R22.2 R24.2 U1.1 U1.6 | length 69.7
  Bottom Layer w0.3: EC2.1 10.55,4.25 11.15,4.25 12.2,5.3 ; 11.75,6.15 12.175,5.725 ; 23.445,15.07 cw(c24,14.515) R24.2@24,15.3 ; R24.2@23.626,15.251 ccw(c23.328,15.55) R24.2@23.75,15.55 ; R24.2@24.177,15.448 cw(c24.604,15.021) 24.604,15.625 cw(c24.604,16.229) R24.2@24.177,15.802 ; C15.1@25.473,15.448 ccw(c25.046,15.021) 25.046,15.625 ccw(c25.046,16.229) C15.1@25.473,15.802 ; C15.1@25.65,15.3 cw(c25.65,14.515) 26.205,15.07 ; C15.1@25.9,15.55 ccw(c26.322,15.55) C15.1@26.024,15.251 ; 38.27,17.405 cw(c37.715,16.85) R22.2@38.5,16.85 ; R22.2@38.451,17.224 ccw(c38.75,17.522) R22.2@38.75,17.1 ; R22.2 37.875,17.8 33.5,17.8 30.85,15.15 30.85,14.354 30.396,13.9 27.375,13.9 C15.1 R24.2 21.55,13.175 21.55,6.5 20.6,5.55 12.45,5.55 ; 12.175,5.725 12.35,5.55 12.45,5.55 ; 12.175,5.725 12.175,5.325 12.2,5.3 ; 12.2,5.3 12.45,5.55
  Bottom Layer w0.4: 22.25,5.05 22.3,5.1 R19.1@22.3,11.85 ; 22.3,9.989 cw(c24.461,9.989) R19.1@22.933,11.517 ; 22.3,10.955 cw(c23.495,10.955) R19.1@22.65,11.8 ; R24.2 C15.1 ; R24.2@24.141,15.484 cw(c24.483,15.142) 24.483,15.625 cw(c24.483,16.108) R24.2@24.141,15.766 ; C15.1@25.509,15.484 ccw(c25.167,15.142) 25.167,15.625 ccw(c25.167,16.108) C15.1@25.509,15.766 ; Q3.2@31.8,7.15 31.8,8.35 33.35,9.9 U1.1@33.35,14.3 ; U1.6@33.209,11.209 cw(c32.867,10.867) 33.35,10.867 cw(c33.833,10.867) U1.6@33.491,11.209 ; U1.6@33.209,11.891 ccw(c32.867,12.233) 33.35,12.233 ccw(c33.833,12.233) U1.6@33.491,11.891 ; U1.1@33.209,14.109 cw(c32.867,13.767) 33.35,13.767 cw(c33.833,13.767) U1.1@33.491,14.109
W: C4.1 C6.2 pad.B@24.9,8.1 Q3.3 R20.1 U1.2 | length 35.3
  Bottom Layer w0.4: Q3.3@29.11,7.25 Q3.3@29.11,7.41 ; C4.1@30.717,11.517 cw(c30.034,10.834) 31,10.834 cw(c31.966,10.834) C4.1@31.283,11.517 ; C4.1 31,10.7 29.4,9.1 29.4,7.54 29.4,7.95 32.3,10.85 32.3,15.1 33.45,16.25 R20.1 34.5,15.825 ; 32.72,15.52 cw(c34,14.239) R20.1@34,16.05 ; 33.403,16.203 cw(c34,15.605) R20.1@34,16.45 ; R20.1@33.859,16.109 ccw(c33.517,15.767) 33.517,16.25 ccw(c33.517,16.733) R20.1@33.859,16.391 ; R20.1@34.009,16.109 cw(c32.822,14.922) U1.2@34.5,14.922 ; R20.1@34.15,16.05 cw(c34.149,15.699) 34.5,15.699 ; R20.1@34.291,16.391 cw(c33.788,15.888) 34.5,15.888 ; R20.1@34.349,16.234 ccw(c34.868,16.193) 34.5,15.825 ; C6.2@37.209,13.134 ccw(c36.867,12.792) 36.867,13.275 ccw(c36.867,13.758) C6.2@37.209,13.416 ; C6.2 35.075,13.275 34.5,13.85 U1.2 34.5,15.825
  Bottom Layer w1: Q3.3@29.11,7.25 Q3.3@29.4,7.54
  Bottom Layer w1.5: pad.B@24.1,7.25 Q3.3@29.11,7.25
pads on no net: J1.0 J2.0 T1.1 T1.2 T1.3 T1.4 T1.5 T1.8

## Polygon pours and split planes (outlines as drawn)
NetCX1_2 on Bottom Layer "Bottom-No Net" (solid, pour order 43): 22.15,71.85 23.85,70.15 26.9,70.15 27.5,69.55 27.5,67.95 27.2,67.65 26.05,67.65 25.4,68.3 22,68.3 21.8,68.5 21.8,69.45 21.7,69.55 21.5,69.55 21.4,69.45 21.4,68.55 21.15,68.3 15.05,68.3 13.45,66.7 12.1,66.7 11.5,67.3 11.5,69.35 12.25,70.1 18.9,70.1 20.65,71.85
NetCX1_1 on Bottom Layer "Bottom-No Net" (solid, pour order 41): 27.2,63.45 27.5,63.15 27.5,61.4 26.95,60.85 23.35,60.85 22.25,59.75 19.4,59.75 18.45,60.7 12.55,60.7 12,61.25 12,62.1 12.6,62.7 19.55,62.7 20.65,61.6 20.85,61.6 20.95,61.7 20.95,61.9 20.65,62.2 20.65,63.1 21,63.45
117 on Bottom Layer "Bottom-No Net" (solid, pour order 39): 31.9,65.5 34.1,65.5 34.5,65.1 34.5,63.35 34.15,63 31.35,63 30.1,61.75 29.75,61.4 29.1,61.4 28.95,61.4 28.7,61.65 28.7,64.65 29.45,65.4 29.55,65.5 31.65,65.5
116 on Bottom Layer "Bottom-No Net" (solid, pour order 37): 32.45,71.45 33.8,71.45 34.05,71.2 34.2,71.05 34.2,70.15 34.2,68.75 33.4,67.95 33.1,67.65 29.85,67.65 29,67.65 28.7,67.95 28.7,69.6 29,69.9 30.05,69.9 30.35,70.2 31.6,71.45 32.35,71.45
NetNTC1_1 on Bottom Layer "Bottom-No Net" (solid, pour order 35): 39.5,65.75 42.1,65.75 42.55,65.3 42.55,63.5 42.05,63 36.25,63 35.7,63.55 35.7,65.35 36,65.65 36.1,65.75 39.25,65.75
NetF1_1 on Bottom Layer "Bottom-No Net" (solid, pour order 33): 40.25,72.15 42.05,72.15 42.6,71.6 42.6,69.65 42.15,69.2 37.9,69.2 37.45,69.65 37.4,69.7 37.4,70.35 37.4,71.6 37.9,72.1 37.95,72.15 40.15,72.15
NetDB1_2 on Bottom Layer "Keep-Out Layer-No Net" (solid, remove dead copper, pour order 37): 7.95,69.05 8.4,68.6 8.4,66.65 7.85,66.1 6.5,66.1 2.5,62.1 0.9,62.1 0.5,62.5 0.5,64.6 0.9,65 2.8,65 6.85,69.05
NetDB1_1 on Bottom Layer "Keep-Out Layer-No Net" (solid, remove dead copper, pour order 38): 7.55,63 7.9,62.65 7.9,60.7 7.55,60.35 5.5,60.35 2.2,57.05 0.9,57.05 0.5,57.45 0.5,59.55 0.8,59.85 2.6,59.85 5.75,63
VIN on Bottom Layer "Keep-Out Layer-No Net" (solid, remove dead copper, pour order 48): 11.75,4.3 11.65,4.4 11.65,4.6 12.1,5.05 12.1,6.45 9.15,6.45 9.1,6.4 9.1,4.9 8.25,4.05 8.25,2 8.95,1.3 19.75,1.3 21.15,2.7 24.3,2.7 26.3,0.7 33.65,0.7 34.15,1.2 34.15,4.45 32.75,5.85 32.75,9.2 32.35,9.2 30.85,7.7 30.85,6.2 29.944,5.294 28.606,5.294 28.1,5.8 23.05,5.8 22.5,6.35 22.2,6.35 20.95,5.1 12.75,5.1 11.95,4.3
NetC12_1 on Bottom Layer "Keep-Out Layer-No Net" (solid, remove dead copper, pour order 49): 29.55,44.45 30.05,43.95 30.05,39.85 30.4,39.2 31.4,38.2 31.4,34.55 31.1,34.25 29.75,34.25 29.45,34.55 29.45,37 29.15,38.25 28.4,39.3 28.4,40.1 27.35,41.15 27.35,43.95 27.85,44.45
NetQ2_G on Bottom Layer "Keep-Out Layer-No Net" (solid, remove dead copper, pour order 56): 36.35,40.85 35.65,40.85 34.45,42.05 33.9,42.05 33.5,42.45 33.5,44.5 34.2,45.2 34.5,45.2 36.35,43.35
NetC11_1 on Bottom Layer "Keep-Out Layer-No Net" (solid, remove dead copper, pour order 57): 32.6,43.2 32.6,41.95 33.1,41.45 33.25,41.3 33.65,41.3 34,41.3 34,40.5 33.25,40.5 32.8,40.05 32.7,39.95 32.35,39.95 31.75,39.95 31.6,40.1 31.55,40.15 31.55,40.75 31.55,41.75 31,42.3 31,43.55 32.35,43.55 32.6,43.3
NetC1_2 on Bottom Layer "Keep-Out Layer-No Net" (solid, remove dead copper, pour order 54): 25.35,31.35 25.5,31.2 25.5,27.6 25.35,27.45 24.45,27.45 24,27.9 17.35,27.9 17.2,28.05 17.2,28.95 17.35,29.1 23.45,29.1 24.3,29.95 24.3,31.2 24.45,31.35
NetD1_2 on Bottom Layer "Keep-Out Layer-No Net" (solid, remove dead copper, pour order 52): 30.15,32.1 31.05,32.1 31.3,31.85 31.35,31.8 31.35,31.45 31.35,30.2 28.6,27.45 28,27.45 27.65,27.45 27.5,27.6 27.5,28.1 27.5,31.2 27.75,31.45 28.4,32.1 29.8,32.1
NetC2_2 on Bottom Layer "Keep-Out Layer-No Net" (solid, remove dead copper, pour order 50): 27,39 27.45,39 27.6,38.85 27.6,38.5 27.6,37.45 27.85,37.2 27.85,36.25 27.85,35.45 26.75,34.35 25.95,33.55 25.35,33.55 23.8,33.55 23.55,33.8 23.25,34.1 23.25,34.45 23.25,35.35 23.55,35.65 23.65,35.75 24.05,35.75 24.95,35.75 26.15,36.95 26.4,37.2 26.4,38.25 26.4,38.8 26.6,39
VIN on Bottom Layer "Keep-Out Layer-No Net" (solid, remove dead copper, pour order 58): 9.1,12.05 9.1,6.15 12.1,6.15 12.1,12.1 9.55,14.65 7.8,14.65 5.8,12.65 5.8,9.05 4.5,7.75 2.25,7.75 1.3,6.8 1.3,2.1 2.1,1.3 7.15,1.3 7.75,1.9 7.75,4.05 8.8,5.1 8.8,12.05 8.9,12.15 9,12.15
SGND on Bottom Layer "Keep-Out Layer-No Net" (solid, remove dead copper, pour order 60): 15.8,17.75 16.3,17.25 16.3,15.45 15.95,15.1 14.8,15.1 12.65,17.25 11.15,17.25 11.05,17.15 11.05,17.05 11.15,16.95 12.5,16.95 14.75,14.7 16.65,14.7 16.65,14.3 16.3,13.95 16.3,10.2 14.55,8.45 14.55,8.35 14.65,8.25 14.8,8.25 16.75,10.2 16.75,11.75 17.25,12.25 20.35,12.25 21.1,11.5 21.1,6.9 20.3,6.1 13,6.1 12.4,6.7 12.4,12.3 9.7,15 7.7,15 5.5,12.8 5.5,9.25 4.3,8.05 1.95,8.05 0.9,7 0.5,7 0.5,14.9 1.35,15.75 4,15.75 4.85,16.6 4.85,16.75 4.75,16.85 4.65,16.85 3.85,16.05 2.35,16.05 1.9,16.5 1.9,17.85 2.4,18.35 7.1,18.35 8.3,17.75
W on Bottom Layer "Keep-Out Layer-No Net" (solid, remove dead copper, pour order 46): 24.95,10.75 30.6,10.75 30.85,11 31.2,11 31.2,10.6 30.5,9.9 29.6,9 29.6,8.75 29.7,8.65 29.85,8.65 29.95,8.75 30.2,8.75 30.2,6.1 29.7,5.6 28.95,5.6 28.8,5.6 28.5,5.9 28.3,6.1 28.2,6.1 23.2,6.1 22.9,6.4 22.9,10.25 23.4,10.75 24.4,10.75
NetQ3_4 on Bottom Layer "Keep-Out Layer-No Net" (solid, remove dead copper, pour order 45): 34.65,9.45 36.25,7.85 36.25,7.15 36.25,5.9 35.7,5.35 34.1,5.35 33.4,6.05 33.4,6.25 33.4,7.75 34,8.35 34.3,8.65 34.3,9.45 34.5,9.45
GND on Bottom Layer "Keep-Out Layer-No Net" (solid, remove dead copper, pour order 36): 3.15,72 5.2,72 5.55,71.65 5.6,71.6 5.6,70.55 5.6,70.15 5.15,69.7 2.7,67.25 1.75,67.25 0.9,67.25 0.5,67.65 0.5,71.6 0.9,72 2.7,72
NetDB1_4 on Bottom Layer "Keep-Out Layer-No Net" (solid, remove dead copper, pour order 40): 2.1,54.7 4.15,52.65 4.15,32.65 6.55,30.25 12.5,30.25 14,31.75 14,34 12,36 12,37.6 12.5,38.1 15.6,38.1 15.7,38 15.7,30.5 13.95,28.75 5.1,28.75 1.75,32.1 1.6,32.1 1.5,32 1.5,31.55 3.8,29.25 3.8,26.55 3.35,26.1 1.3,26.1 0.5,26.9 0.5,42.95 1.3,43.75 1.3,44.1 0.5,44.9 0.5,54.3 0.9,54.7
HV on Bottom Layer "Keep-Out Layer-No Net" (solid, remove dead copper, pour order 42): 18.5,48.8 19.85,47.45 19.85,36.8 21.05,35.6 21.05,31.35 20.8,31.1 17.7,31.1 17.2,31.6 17.2,38.7 16.3,39.6 16.3,46.05 16.2,46.15 16.05,46.15 15.9,46 15.9,39.45 15.65,39.2 12.4,39.2 12,39.6 12,41.95 13.4,43.35 13.4,47.8 14.4,48.8
GND on Bottom Layer "Keep-Out Layer-No Net" (solid, remove dead copper, pour order 39): 7.25,56.8 8.45,55.6 8.45,45.35 8.55,45.25 8.65,45.25 8.75,45.35 8.75,51.25 12.1,54.6 21.05,54.6 21.4,54.25 21.4,52.75 19.4,50.75 13.95,50.75 11.6,48.4 11.6,44.05 10.2,42.65 10.2,34.55 10,34.35 9.1,34.35 9,34.25 9,34.1 9.1,34 11.85,34 12.5,33.35 12.5,32.5 12,32 7.15,32 5.7,33.45 5.7,53.25 3.7,55.25 3.7,55.85 4.65,56.8
GND on Bottom Layer "Keep-Out Layer-No Net" (solid, remove dead copper, pour order 47): 40.85,34.75 40.85,33.55 40.25,32.95 38.4,32.95 37.85,33.5 37.85,35.25 37.4,35.7 37.35,35.75 37.35,36.2 40.45,36.2 40.8,35.85 40.85,35.8 40.85,35.15
NetC7_1 on Bottom Layer "Keep-Out Layer-No Net" (solid, remove dead copper, pour order 51): 41,53.75 41,53.05 40.7,52.75 40.6,52.65 40.25,52.65 39.45,52.65 39.2,52.9 39.2,54.05 39.75,54.6 39.75,55.2 40.4,55.2 40.4,54.7 40.7,54.4 41,54.1 41,53.9
GND on Bottom Layer "Keep-Out Layer-No Net" (solid, remove dead copper, pour order 53): 41.7,51.35 40.7,50.35 40.35,50.35 40.15,50.15 39.8,50.15 39.8,50.4 39.3,50.9 38.95,50.9 37.7,49.65 37.45,49.65 37.45,50.95 36.8,51.6 36.8,51.8 37.6,51.8 38.65,52.85 38.9,52.85 38.9,52.3 38,51.4 38,51.25 38.1,51.15 38.25,51.15 39.25,52.15 40.6,52.15 41.35,52.9 41.7,52.9
GND on Bottom Layer "Keep-Out Layer-No Net" (solid, remove dead copper, pour order 55): 35.85,58.25 35.55,58.25 33.3,56 31.5,56 29.7,54.2 20.65,54.2 20.65,54.55 21.7,55.6 29.55,55.6 32.6,58.65 35.9,58.65 35.9,58.3
SGND on Bottom Layer "Keep-Out Layer-No Net" (solid, remove dead copper, pour order 59): 24.15,2.4 25.35,1.2 25.35,0.75 25.1,0.5 19.9,0.5 19.9,1 21.3,2.4
GND on Bottom Layer "Keep-Out Layer-No Net" (solid, remove dead copper, pour order 41): 14.65,27.25 15.1,26.8 15.1,25.35 14.7,24.95 10.9,24.95 10.4,25.45 10.4,26.8 10.85,27.25
GND on Bottom Layer "Keep-Out Layer-No Net" (solid, remove dead copper, pour order 43): 28.55,53.9 29.1,53.35 29.1,50.2 28.65,49.75 23.2,49.75 21.35,51.6 21.25,51.6 21.15,51.5 21.15,51.3 22.4,50.05 22.4,45.2 24.75,42.85 24.75,37.75 24.25,37.25 21.85,37.25 21.4,37.7 21.4,49.15 20.1,50.45 20.1,51.15 20,51.25 19.75,51.25 19.75,54.05 20.3,54.6 21.55,54.6 21.55,54.2 21.45,54.1 21.45,54 21.55,53.9
NetC11_1 on Bottom Layer "Keep-Out Layer-No Net" (solid, remove dead copper, pour order 44): 30.85,48.65 32.6,46.9 32.6,42.35 32.15,41.9 31.4,41.9 31,42.3 31,44.9 29.7,46.2 23.1,46.2 22.75,46.55 22.75,48.35 23.05,48.65 25.45,48.65 26.2,49.4 26.6,49.4 26.6,49 26.4,49 26.3,48.9 26.3,48.8 26.45,48.65
NetR9_2 on Bottom Layer "Keep-Out Layer-No Net" (solid, remove dead copper, pour order 61): 36.25,34.7 36.25,33.4 35.85,33 35.8,32.95 35.6,32.95 33.75,32.95 33.55,33.15 33.4,33.3 33.4,34 33.4,35.95 33.85,36.4 34.45,37 34.45,37.35 35.65,37.35 35.65,36.55 35.95,36.25 36.25,35.95 36.25,35

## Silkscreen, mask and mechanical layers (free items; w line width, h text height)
Top Overlay:
  circle w0.12: c31.8,2.85 r1
  circle w0.12: c31.8,39.5 r1
  circle w0.2: c3.8,3.8 r2.6
  circle w0.2: c3,11.15 r2.6
  lines w0.12: 31.8,1.85 31.8,3.85 ; 31.8,38.5 31.8,40.5
  lines w0.2: 18.55,1.85 42.55,1.85 42.55,3.85 18.55,3.85 18.55,1.85 ; 18.55,38.5 42.55,38.5 42.55,40.5 18.55,40.5 18.55,38.5
  text "L" at 41.2,67.9 h1.5
  text "N" at 40.35,61.5 h1.5
  text "HOT" at 30.15,55.85 h2
  text "GSD" at 30.5,51.1 h1.5
  text "PCB:65W" at 28.4,48.65 h1
  text "REV0.3 221223" at 28.4,47.312 h1
  text "V-" at 0.6,14.05 h1
  text "V+" at 0.55,6.2 h1
  text "B" at 18.4,4.55 h1.5
  text "A" at 24.25,4.5 h1.5
Bottom Overlay:
  drawing of 4180 lines, arcs and shapes, not listed
  text "HOT" at 37.3,59.7 h2
  text "COLD" at 41.7,1.9 h1.8
Bottom Solder:
  drawing of 273 lines, arcs and shapes, not listed
Mechanical 1:
  lines w0.1: 0,1 ccw(c1,1) 1,0 33.4,0 36.8,0 42.1,0 ccw(c42.1,1) 43.1,1 43.1,71.7 ccw(c42.1,71.7) 42.1,72.7 29.7,72.7 29.7,70.4 27.7,70.4 27.7,72.7 18.4,72.7 18.4,70.4 16.4,70.4 16.4,72.7 1,72.7 ccw(c1,71.7) 0,71.7 0,1
Mechanical 2:
  lines w1.2: 29.55,45.45 30.55,44.45 ; 30.7,41.1 30.7,40.1 31.9,38.9 33.1,38.9
  lines w1.5: 0.4,55.5 2.35,55.5 4.9,52.95 4.9,33.05 6.6,31.35 ; 5.5,68.95 6.35,69.8 6.35,71.85 ; 13.25,32.35 13.25,33.65 11.2,35.7 11.2,42.3 12.55,43.65 12.55,48.2 13.6,49.25 ; 19.75,48.55 20.6,47.7 20.6,37.25 21.65,36.2 21.65,34.65 23.5,32.8 26.35,32.8 ; 22.85,36.05 23.3,36.5 24.6,36.5 25.6,37.5 25.6,40.25 ; 27.65,45.45 29.55,45.45 ; 30.55,43.25 30.55,44.45
  lines w1.8: 10.625,66.525 11.35,65.8 13.8,65.8 15.35,67.35 24.85,67.35 25.9,66.3 ; 11.1,61.5 11.1,62.5 12.2,63.6 14.25,63.6
  lines w3: 15.95,59.7 17.1,59.7 18.6,58.2 28.7,58.2 31.9,61.4 42.55,61.4 44.15,59.8
  lines w3.2: 36.3,75.6 35.8,75.1 35.8,69 37.3,67.5 47.7,67.5
  lines w7.2: -0.05,22.35 8.25,22.35 9.25,21.35 16.25,21.35 18.4,23.5 29.85,23.5 31.4,25.05 45.95,25.05 46.25,25.35
Mechanical 3:
  lines w0.005: 205.55,-0.55 199.25,-0.55 ; 199.25,-0.55 199.25,5.25 195.85,5.25 195.85,-0.55 163.45,-0.55 cw(c163.45,0.45) 162.45,0.45 162.45,71.15 cw(c163.45,71.15) 163.45,72.15 176.85,72.15 176.85,69.85 178.85,69.85 178.85,72.15 189.15,72.15 189.15,69.85 191.15,69.85 191.15,72.15 204.55,72.15 cw(c204.55,71.15) 205.55,71.15 205.55,0.45 cw(c204.55,0.45) 204.55,-0.55 199.25,-0.55 ; 243.121,-0.55 243.121,72.15 244.321,72.15 244.321,-0.55 243.121,-0.55
Drill Drawing:
  text ".Legend" at -6.5,77.65 h1.5

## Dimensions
0,71.7 to 43.1,71.7 on Drill Drawing
42.1,72.7 to 42.1,0 on Drill Drawing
